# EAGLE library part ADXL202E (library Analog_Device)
+/- 2g Dual-Axis Accelerometer with Duty Cycle Output
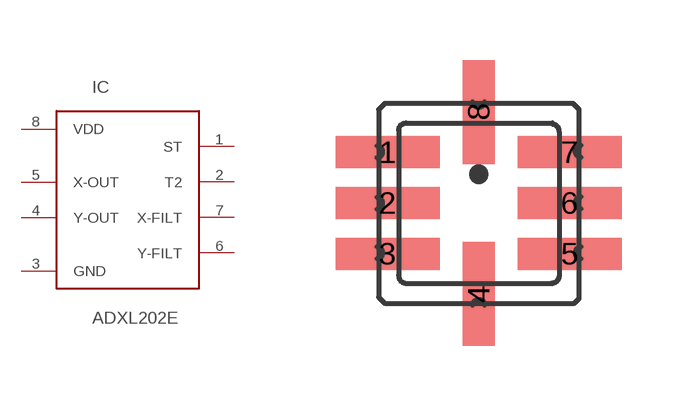
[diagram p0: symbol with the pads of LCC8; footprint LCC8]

Designator prefix IC

## ADXL202E  [LCC8]
1  ST  in
2  T2  in
3  GND  pwr
4  Y-OUT  out
5  X-OUT  out
6  Y-FILT  in
7  X-FILT  in
8  VDD  pwr

## Footprint LCC8 (pad centres in mm)
8 - Terminal Ceramic Leadless Chip Carrier (LCC)
smd 2.6 x 0.8: 1 -2.28,1.27; 2 -2.28,0; 3 -2.28,-1.27; 5 2.27,-1.27; 6 2.27,0; 7 2.27,1.27
smd 0.8 x 2.6: 4 0,-2.28; 8 0,2.28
